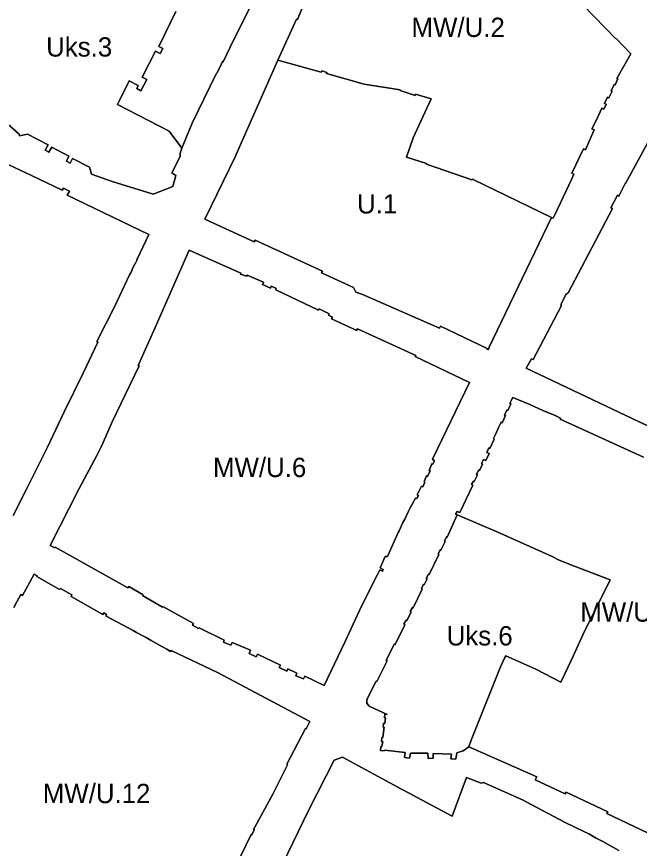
# Model space of a CAD drawing. Extents: x 7423367 to 7424726, y 5546744 to 5548391.
# Drawn here: x 7423927 to 7424088.2, y 5547952.8 to 5548168.2 of the extents above; entities that cross this region are included whole.
import ezdxf

# ---------------------------------------------------------------- set-up
doc = ezdxf.new("R2010")
doc.units = 0
doc.layers.add('linie_rozgraniczajace', color=7, linetype='Continuous')
doc.layers.add('oznaczenia_przeznaczen', color=7, linetype='Continuous')

msp = doc.modelspace()

# ---------------------------------------------------------------- linework, layer by layer
at = {"layer": 'linie_rozgraniczajace'}
for points in [[(7424003.19, 5548176.02), (7423999.73, 5548167.51), (7423999.51, 5548167.58), (7423994.64, 5548156.97), (7423983.83, 5548132.55), (7423983.76, 5548132.31), (7423975.74, 5548115.8), (7423988.5, 5548109.91), (7423988.77, 5548110.31), (7424006.16, 5548102.33), (7424005.96, 5548101.91), (7424014.24, 5548098.09), (7424014.8, 5548096.87), (7424016.34, 5548096.32), (7424036.46, 5548087.52), (7424036.71, 5548088.08), (7424048.82, 5548082.3), (7424048.77, 5548082.15), (7424049.19, 5548082), (7424049.38, 5548082.39), (7424049.28, 5548082.44), (7424065.51, 5548116.2), (7424065.9, 5548116.05), (7424066.35, 5548116.88), (7424070.65, 5548126.07), (7424071.24, 5548127.45), (7424070.72, 5548127.67), (7424073.78, 5548133.99), (7424074.27, 5548133.75), (7424076.5, 5548138.89), (7424075.92, 5548139.15), (7424077.25, 5548141.67), (7424078.55, 5548144.53), (7424079, 5548144.31), (7424079.63, 5548145.59), (7424079.24, 5548145.78), (7424079.99, 5548147.37), (7424080.34, 5548147.2), (7424081.19, 5548148.92), (7424080.9, 5548149.06), (7424081.71, 5548150.66), (7424081.98, 5548150.55), (7424082.62, 5548152.12), (7424082.42, 5548152.2), (7424086.01, 5548158.62), (7424082.2, 5548162.54), (7424082.1, 5548162.45), (7424073.67, 5548171.21)], [(7424073.67, 5548171.21), (7424082.1, 5548162.45), (7424082.2, 5548162.54), (7424086.01, 5548158.62), (7424082.42, 5548152.2), (7424082.62, 5548152.12), (7424081.98, 5548150.55), (7424081.71, 5548150.66), (7424080.9, 5548149.06), (7424081.19, 5548148.92), (7424080.34, 5548147.2), (7424079.99, 5548147.37), (7424079.24, 5548145.78), (7424079.63, 5548145.59), (7424079, 5548144.31), (7424078.55, 5548144.53), (7424077.25, 5548141.67), (7424075.92, 5548139.15), (7424076.5, 5548138.89), (7424074.27, 5548133.75), (7424073.78, 5548133.99), (7424070.72, 5548127.67), (7424071.24, 5548127.45), (7424070.65, 5548126.07), (7424066.35, 5548116.88), (7424065.9, 5548116.05), (7424065.51, 5548116.2), (7424045.18, 5548126.03), (7424044.95, 5548126.11), (7424044.88, 5548125.95), (7424033.08, 5548130.03), (7424033.14, 5548130.2), (7424027.94, 5548131.81), (7424029.66, 5548136.83), (7424032.73, 5548143.39), (7424034.34, 5548146.95), (7424030.28, 5548148.18), (7424030.19, 5548147.85), (7424026.28, 5548149.12), (7424026.31, 5548149.25), (7424016.95, 5548150.75), (7424007.21, 5548153.49), (7424007.34, 5548153.8), (7424006.03, 5548154.22), (7424005.87, 5548153.89), (7423994.64, 5548156.97), (7423999.51, 5548167.58), (7423999.73, 5548167.51), (7424003.19, 5548176.02)], [(7423918.17, 5548146.1), (7423927.64, 5548137.8), (7423927.77, 5548137.36), (7423929.82, 5548137.78), (7423935.15, 5548135.03), (7423934.4, 5548133.64), (7423935.37, 5548133.12), (7423936.1, 5548134.43), (7423940.56, 5548132.06), (7423939.91, 5548130.76), (7423940.91, 5548130.26), (7423941.51, 5548131.46), (7423945.92, 5548129.26), (7423946.39, 5548127.41), (7423951.76, 5548125.57), (7423962.14, 5548122.36), (7423962.41, 5548122.28), (7423967.48, 5548124.28), (7423968.22, 5548127.09), (7423967.24, 5548127.78), (7423969.33, 5548131.97), (7423969.39, 5548132.86), (7423969.78, 5548134.19), (7423972.47, 5548140.65), (7423978.69, 5548153.44), (7423978.76, 5548153.53), (7423978.82, 5548153.61), (7423979.76, 5548155.37), (7423980.33, 5548156.58), (7423980.53, 5548156.49), (7423983.16, 5548162.13), (7423989.62, 5548175.07)], [(7423989.62, 5548175.07), (7423983.16, 5548162.13), (7423980.53, 5548156.49), (7423980.33, 5548156.58), (7423979.76, 5548155.37), (7423978.82, 5548153.61), (7423978.76, 5548153.53), (7423978.69, 5548153.44), (7423972.47, 5548140.65), (7423969.78, 5548134.19), (7423966.54, 5548138.57), (7423953.16, 5548145.44), (7423953.66, 5548146.48), (7423956.13, 5548151.59), (7423958.5, 5548150.36), (7423958.11, 5548149.63), (7423959.2, 5548149.06), (7423960.72, 5548151.95), (7423959.54, 5548152.58), (7423962.98, 5548159.27), (7423964.18, 5548158.65), (7423964.86, 5548159.95), (7423963.82, 5548160.49), (7423968.21, 5548169.56)], [(7423968.21, 5548169.56), (7423963.82, 5548160.49), (7423964.86, 5548159.95), (7423964.18, 5548158.65), (7423962.98, 5548159.27), (7423959.54, 5548152.58), (7423960.72, 5548151.95), (7423959.2, 5548149.06), (7423958.11, 5548149.63), (7423958.5, 5548150.36), (7423956.13, 5548151.59), (7423953.66, 5548146.48), (7423953.16, 5548145.44), (7423966.54, 5548138.57), (7423969.78, 5548134.19), (7423969.39, 5548132.86), (7423969.33, 5548131.97), (7423967.24, 5548127.78), (7423968.22, 5548127.09), (7423967.48, 5548124.28), (7423962.41, 5548122.28), (7423962.14, 5548122.36), (7423951.76, 5548125.57), (7423946.39, 5548127.41), (7423945.92, 5548129.26), (7423941.51, 5548131.46), (7423940.91, 5548130.26), (7423939.91, 5548130.76), (7423940.56, 5548132.06), (7423936.1, 5548134.43), (7423935.37, 5548133.12), (7423934.4, 5548133.64), (7423935.15, 5548135.03), (7423929.82, 5548137.78), (7423927.77, 5548137.36), (7423927.64, 5548137.8), (7423918.17, 5548146.1)], [(7424090.24, 5548062.32), (7424088.17, 5548063.25), (7424058.95, 5548077.17), (7424060.29, 5548079.6), (7424060.73, 5548079.4), (7424067.99, 5548093.25), (7424067.99, 5548093.87), (7424069.27, 5548096.37), (7424069.8, 5548096.72), (7424073.3, 5548103.4), (7424081.29, 5548118.54), (7424080.88, 5548118.7), (7424082.56, 5548121.98), (7424082.95, 5548121.78), (7424084.54, 5548125.06), (7424084.67, 5548124.99), (7424090.84, 5548136.42)], [(7424090.84, 5548136.42), (7424084.67, 5548124.99), (7424084.54, 5548125.06), (7424082.95, 5548121.78), (7424082.56, 5548121.98), (7424080.88, 5548118.7), (7424081.29, 5548118.54), (7424073.3, 5548103.4), (7424069.8, 5548096.72), (7424069.27, 5548096.37), (7424067.99, 5548093.87), (7424067.99, 5548093.25), (7424060.73, 5548079.4), (7424060.29, 5548079.6), (7424058.95, 5548077.17), (7424088.17, 5548063.25), (7424090.24, 5548062.32)], [(7423922.01, 5548131.22), (7423930.85, 5548127.09), (7423938.84, 5548123.29), (7423939.13, 5548123.84), (7423940.68, 5548123.04), (7423940.15, 5548122.03), (7423961.23, 5548111.84), (7423958.12, 5548105.29), (7423958.19, 5548105.25), (7423957.68, 5548104.22), (7423957.63, 5548104.24), (7423956.93, 5548102.78), (7423957, 5548102.74), (7423956.54, 5548101.77), (7423956.47, 5548101.8), (7423956.27, 5548101.4), (7423952.32, 5548093.08), (7423947.8, 5548084.06), (7423948.08, 5548083.92), (7423944.27, 5548075.86), (7423939.3, 5548065.9), (7423934.99, 5548056.7), (7423931.08, 5548048.8), (7423929.48, 5548045.71), (7423926.14, 5548039.05)], [(7423926.14, 5548039.05), (7423929.48, 5548045.71), (7423931.08, 5548048.8), (7423934.99, 5548056.7), (7423939.3, 5548065.9), (7423944.27, 5548075.86), (7423948.08, 5548083.92), (7423947.8, 5548084.06), (7423952.32, 5548093.08), (7423956.27, 5548101.4), (7423956.47, 5548101.8), (7423956.54, 5548101.77), (7423957, 5548102.74), (7423956.93, 5548102.78), (7423957.63, 5548104.24), (7423957.68, 5548104.22), (7423958.19, 5548105.25), (7423958.12, 5548105.29), (7423961.23, 5548111.84), (7423940.15, 5548122.03), (7423940.68, 5548123.04), (7423939.13, 5548123.84), (7423938.84, 5548123.29), (7423930.85, 5548127.09), (7423922.01, 5548131.22)], [(7424089.25, 5548054.14), (7424067.71, 5548063.98), (7424067.84, 5548064.27), (7424066.42, 5548064.89), (7424063.24, 5548066.21), (7424059.91, 5548067.76), (7424055.5, 5548069.62), (7424054.73, 5548068.11), (7424054.98, 5548067.99), (7424054.17, 5548066.18), (7424053.9, 5548066.31), (7424053.3, 5548065.02), (7424053.53, 5548064.91), (7424052.68, 5548063.07), (7424052.44, 5548063.18), (7424051.87, 5548061.97), (7424050.97, 5548060.03), (7424050.43, 5548058.94), (7424050.66, 5548058.82), (7424049.54, 5548056.39), (7424049.27, 5548056.52), (7424048.73, 5548055.37), (7424049.33, 5548055.09), (7424048.49, 5548053.23), (7424047.89, 5548053.53), (7424047.37, 5548052.46), (7424047.61, 5548052.34), (7424046.82, 5548050.67), (7424046.59, 5548050.78), (7424046.05, 5548049.67), (7424046.31, 5548049.54), (7424045.48, 5548047.81), (7424045.25, 5548047.92), (7424044.8, 5548047.03), (7424045.14, 5548046.88), (7424041.78, 5548039.84), (7424041.04, 5548040.08), (7424040.67, 5548039.4), (7424041.08, 5548039.21), (7424038.48, 5548033.42), (7424038.31, 5548033.5), (7424037.76, 5548032.37), (7424037.94, 5548032.29), (7424036.87, 5548030.07), (7424036.68, 5548030.16), (7424036.15, 5548029), (7424036.33, 5548028.96), (7424033.82, 5548023.76), (7424033.63, 5548023.85), (7424033.06, 5548022.68), (7424033.26, 5548022.59), (7424032.55, 5548021.1), (7424032.34, 5548021.2), (7424031.79, 5548020.03), (7424031.99, 5548019.93), (7424029.68, 5548015.1), (7424029.46, 5548015.2), (7424028.93, 5548014.13), (7424029.16, 5548014.02), (7424028.05, 5548011.81), (7424027.83, 5548011.93), (7424027.29, 5548010.86), (7424027.51, 5548010.74), (7424025, 5548005.64), (7424024.79, 5548005.74), (7424022.69, 5548001.51), (7424022.91, 5548001.4), (7424020.27, 5547996.03), (7424020.05, 5547996.13), (7424017.69, 5547991.38), (7424017.71, 5547990.4), (7424018.28, 5547989.68), (7424022.95, 5547987.45), (7424022.36, 5547987.53), (7424022.24, 5547986.61), (7424022.52, 5547986.58), (7424022.33, 5547985.19), (7424022.03, 5547985.23), (7424021.92, 5547984.22), (7424022.2, 5547984.2), (7424021.86, 5547981.52), (7424021.57, 5547981.52), (7424021.49, 5547980.47), (7424021.79, 5547980.45), (7424021.58, 5547979.16), (7424021.31, 5547979.18), (7424021.23, 5547978.17), (7424022.21, 5547978.06), (7424022.28, 5547978.28), (7424027.59, 5547977.64), (7424027.42, 5547976.32), (7424028.75, 5547976.14), (7424028.94, 5547977.45), (7424033.51, 5547977.46), (7424033.57, 5547976.12), (7424034.87, 5547976.18), (7424034.89, 5547977.4), (7424039.56, 5547977.23), (7424039.4, 5547975.96), (7424040.71, 5547975.88), (7424040.98, 5547977.54), (7424042.64, 5547978.08), (7424044.04, 5547979.13), (7424061.65, 5547971.38), (7424061.27, 5547970.58), (7424069.01, 5547966.94), (7424069.24, 5547967.38), (7424080.03, 5547962.26), (7424079.83, 5547961.85), (7424092.32, 5547955.87)], [(7424092.32, 5547955.87), (7424079.83, 5547961.85), (7424080.03, 5547962.26), (7424069.24, 5547967.38), (7424069.01, 5547966.94), (7424061.27, 5547970.58), (7424061.65, 5547971.38), (7424044.04, 5547979.13), (7424044.69, 5547980.82), (7424052.24, 5547999.79), (7424053.43, 5548002.26), (7424053.65, 5548002.71), (7424061.43, 5547999.21), (7424067.9, 5547995.9), (7424068.99, 5547998.17), (7424071.1, 5548002.6), (7424073.69, 5548008.28), (7424075.44, 5548011.81), (7424079.87, 5548020.74), (7424080.69, 5548022.4), (7424070.04, 5548026.38), (7424067.33, 5548027.53), (7424065.69, 5548028.41), (7424051.6, 5548034.75), (7424041.08, 5548039.21), (7424040.67, 5548039.4), (7424041.04, 5548040.08), (7424041.78, 5548039.84), (7424045.14, 5548046.88), (7424044.8, 5548047.03), (7424045.25, 5548047.92), (7424045.48, 5548047.81), (7424046.31, 5548049.54), (7424046.05, 5548049.67), (7424046.59, 5548050.78), (7424046.82, 5548050.67), (7424047.61, 5548052.34), (7424047.37, 5548052.46), (7424047.89, 5548053.53), (7424048.49, 5548053.23), (7424049.33, 5548055.09), (7424048.73, 5548055.37), (7424049.27, 5548056.52), (7424049.54, 5548056.39), (7424050.66, 5548058.82), (7424050.43, 5548058.94), (7424050.97, 5548060.03), (7424051.87, 5548061.97), (7424052.44, 5548063.18), (7424052.68, 5548063.07), (7424053.53, 5548064.91), (7424053.3, 5548065.02), (7424053.9, 5548066.31), (7424054.17, 5548066.18), (7424054.98, 5548067.99), (7424054.73, 5548068.11), (7424055.5, 5548069.62), (7424059.91, 5548067.76), (7424063.24, 5548066.21), (7424066.42, 5548064.89), (7424067.84, 5548064.27), (7424067.71, 5548063.98), (7424089.25, 5548054.14)], [(7423926.3, 5548015.23), (7423927.11, 5548016.65), (7423928.13, 5548018.54), (7423928.52, 5548018.33), (7423931.54, 5548023.87), (7423932.37, 5548023.44), (7423932.28, 5548023.27), (7423938.14, 5548019.84), (7423938.34, 5548020.12), (7423941.33, 5548018.46), (7423941.17, 5548018.08), (7423949.35, 5548013.42), (7423949.57, 5548013.81), (7423950.3, 5548013.4), (7423950.16, 5548012.99), (7423957.15, 5548009.26), (7423958.03, 5548008.76), (7423959.53, 5548007.94), (7423960.52, 5548007.41), (7423961.86, 5548006.68), (7423964.62, 5548005.12), (7423965.91, 5548004.37), (7423966.88, 5548003.76), (7423967.04, 5548004.07), (7423979.03, 5547998.32), (7423981.96, 5547996.81), (7424002.91, 5547985.65), (7424002, 5547983.75), (7424001.78, 5547983.86), (7423996.93, 5547974.64), (7423997.15, 5547974.46), (7423993.33, 5547966.87), (7423988.69, 5547958.27), (7423988.35, 5547957.68), (7423988.54, 5547957.58), (7423987.92, 5547956.3), (7423987.74, 5547956.39), (7423983.64, 5547948.01)], [(7423983.64, 5547948.01), (7423987.74, 5547956.39), (7423987.92, 5547956.3), (7423988.54, 5547957.58), (7423988.35, 5547957.68), (7423988.69, 5547958.27), (7423993.33, 5547966.87), (7423997.15, 5547974.46), (7423996.93, 5547974.64), (7424001.78, 5547983.86), (7424002, 5547983.75), (7424002.91, 5547985.65), (7423981.96, 5547996.81), (7423979.03, 5547998.32), (7423967.04, 5548004.07), (7423966.88, 5548003.76), (7423965.91, 5548004.37), (7423964.62, 5548005.12), (7423961.86, 5548006.68), (7423960.52, 5548007.41), (7423959.53, 5548007.94), (7423958.03, 5548008.76), (7423957.15, 5548009.26), (7423950.16, 5548012.99), (7423950.3, 5548013.4), (7423949.57, 5548013.81), (7423949.35, 5548013.42), (7423941.17, 5548018.08), (7423941.33, 5548018.46), (7423938.34, 5548020.12), (7423938.14, 5548019.84), (7423932.28, 5548023.27), (7423932.37, 5548023.44), (7423931.54, 5548023.87), (7423928.52, 5548018.33), (7423928.13, 5548018.54), (7423927.11, 5548016.65), (7423926.3, 5548015.23)], [(7423993.29, 5547943.33), (7424002.7, 5547962.78), (7424009.23, 5547975.62), (7424011.37, 5547976.47), (7424026.69, 5547968.15), (7424028.77, 5547967.02), (7424030.56, 5547966.05), (7424039.78, 5547961.19), (7424043.49, 5547971.15), (7424047.26, 5547969.66), (7424047.89, 5547969.87), (7424058.14, 5547965.31), (7424060.22, 5547964.16), (7424069.04, 5547959.48), (7424073.85, 5547957.18), (7424075.33, 5547956.45), (7424076.9, 5547955.58), (7424078.23, 5547954.89), (7424078.76, 5547954.61), (7424082.89, 5547952.26)], [(7424082.89, 5547952.26), (7424078.76, 5547954.61), (7424078.23, 5547954.89), (7424076.9, 5547955.58), (7424075.33, 5547956.45), (7424073.85, 5547957.18), (7424069.04, 5547959.48), (7424060.22, 5547964.16), (7424058.14, 5547965.31), (7424047.89, 5547969.87), (7424047.26, 5547969.66), (7424043.49, 5547971.15), (7424039.78, 5547961.19), (7424030.56, 5547966.05), (7424028.77, 5547967.02), (7424026.69, 5547968.15), (7424011.37, 5547976.47), (7424009.23, 5547975.62), (7424002.7, 5547962.78), (7423993.29, 5547943.33)]]:
    msp.add_lwpolyline(points, dxfattribs=at)
for points in [[(7423975.74, 5548115.8), (7423983.76, 5548132.31), (7423983.83, 5548132.55), (7423994.64, 5548156.97), (7424005.87, 5548153.89), (7424006.03, 5548154.22), (7424007.34, 5548153.8), (7424007.21, 5548153.49), (7424016.95, 5548150.75), (7424026.31, 5548149.25), (7424026.28, 5548149.12), (7424030.19, 5548147.85), (7424030.28, 5548148.18), (7424034.34, 5548146.95), (7424032.73, 5548143.39), (7424029.66, 5548136.83), (7424027.94, 5548131.81), (7424033.14, 5548130.2), (7424033.08, 5548130.03), (7424044.88, 5548125.95), (7424044.95, 5548126.11), (7424045.18, 5548126.03), (7424065.51, 5548116.2), (7424049.28, 5548082.44), (7424049.38, 5548082.39), (7424049.19, 5548082), (7424048.77, 5548082.15), (7424048.82, 5548082.3), (7424036.71, 5548088.08), (7424036.46, 5548087.52), (7424016.34, 5548096.32), (7424014.8, 5548096.87), (7424014.24, 5548098.09), (7424005.96, 5548101.91), (7424006.16, 5548102.33), (7423988.77, 5548110.31), (7423988.5, 5548109.91)], [(7423935.7, 5548031.28), (7423943.15, 5548045.84), (7423947.87, 5548054.71), (7423948.87, 5548056.79), (7423950.1, 5548059.46), (7423950.29, 5548059.9), (7423951.49, 5548062.65), (7423951.79, 5548063.33), (7423958.76, 5548077.75), (7423958.5, 5548077.86), (7423962.87, 5548087.75), (7423971.69, 5548107.76), (7423985.09, 5548101.79), (7423984.98, 5548101.51), (7423986.5, 5548101), (7423986.68, 5548101.3), (7423990.93, 5548099.45), (7423990.7, 5548098.84), (7423992.73, 5548097.95), (7423992.95, 5548098.44), (7423994.16, 5548097.9), (7423994.14, 5548097.45), (7424005.13, 5548092.17), (7424005.3, 5548092.53), (7424007.96, 5548091.26), (7424007.79, 5548090.9), (7424008.76, 5548090.43), (7424008.55, 5548089.98), (7424014.12, 5548087.4), (7424015.04, 5548086.95), (7424015.25, 5548087.4), (7424030.32, 5548080.47), (7424030.22, 5548080.25), (7424044.27, 5548073.5), (7424034.67, 5548053.63), (7424035.15, 5548053.2), (7424034.76, 5548052.31), (7424034.53, 5548052.41), (7424033.81, 5548050.72), (7424034.07, 5548050.59), (7424033.35, 5548049.16), (7424033.08, 5548049.29), (7424032.48, 5548047.81), (7424032.73, 5548047.7), (7424032.2, 5548046.46), (7424031.83, 5548046.62), (7424030.74, 5548044.4), (7424031.09, 5548044.18), (7424030.62, 5548043.45), (7424030.28, 5548043.55), (7424028.92, 5548041), (7424028.45, 5548040.12), (7424027.53, 5548038.08), (7424027, 5548037.18), (7424026.02, 5548035.09), (7424025.78, 5548034.63), (7424023.01, 5548028.39), (7424022.45, 5548028.37), (7424021.17, 5548025.47), (7424021.93, 5548025.05), (7424021.69, 5548024.63), (7424021.04, 5548024.99), (7424020.34, 5548023.59), (7424016.28, 5548015.51), (7424011.95, 5548006.2), (7424006.63, 5547995.03), (7424001.64, 5547997.4), (7424001.28, 5547996.68), (7423999.29, 5547997.53), (7423999.57, 5547998.18), (7423997.26, 5547999.3), (7423996.96, 5547998.73), (7423995.02, 5547999.67), (7423995.32, 5548000.3), (7423989.38, 5548003.07), (7423989.06, 5548002.45), (7423987.2, 5548003.32), (7423987.58, 5548004.14), (7423982.81, 5548006.14), (7423982.51, 5548005.45), (7423980.61, 5548006.24), (7423980.77, 5548006.71), (7423974.26, 5548009.9), (7423974.09, 5548009.72), (7423972.53, 5548010.63), (7423972.78, 5548011.06), (7423964.83, 5548015.45), (7423964.76, 5548015.32), (7423959.62, 5548018.29), (7423959.75, 5548018.5), (7423956.03, 5548020.6), (7423955.78, 5548020.26), (7423936.99, 5548030.79), (7423936.92, 5548030.66)], [(7423935.7, 5548031.28), (7423936.92, 5548030.66), (7423936.99, 5548030.79), (7423955.78, 5548020.26), (7423956.03, 5548020.6), (7423959.75, 5548018.5), (7423959.62, 5548018.29), (7423964.76, 5548015.32), (7423964.83, 5548015.45), (7423972.78, 5548011.06), (7423972.53, 5548010.63), (7423974.09, 5548009.72), (7423974.26, 5548009.9), (7423980.77, 5548006.71), (7423980.61, 5548006.24), (7423982.51, 5548005.45), (7423982.81, 5548006.14), (7423987.58, 5548004.14), (7423987.2, 5548003.32), (7423989.06, 5548002.45), (7423989.38, 5548003.07), (7423995.32, 5548000.3), (7423995.02, 5547999.67), (7423996.96, 5547998.73), (7423997.26, 5547999.3), (7423999.57, 5547998.18), (7423999.29, 5547997.53), (7424001.28, 5547996.68), (7424001.64, 5547997.4), (7424006.63, 5547995.03), (7424011.95, 5548006.2), (7424016.28, 5548015.51), (7424020.34, 5548023.59), (7424021.04, 5548024.99), (7424021.69, 5548024.63), (7424021.93, 5548025.05), (7424021.17, 5548025.47), (7424022.45, 5548028.37), (7424023.01, 5548028.39), (7424025.78, 5548034.63), (7424026.02, 5548035.09), (7424027, 5548037.18), (7424027.53, 5548038.08), (7424028.45, 5548040.12), (7424028.92, 5548041), (7424030.28, 5548043.55), (7424030.62, 5548043.45), (7424031.09, 5548044.18), (7424030.74, 5548044.4), (7424031.83, 5548046.62), (7424032.2, 5548046.46), (7424032.73, 5548047.7), (7424032.48, 5548047.81), (7424033.08, 5548049.29), (7424033.35, 5548049.16), (7424034.07, 5548050.59), (7424033.81, 5548050.72), (7424034.53, 5548052.41), (7424034.76, 5548052.31), (7424035.15, 5548053.2), (7424034.67, 5548053.63), (7424044.27, 5548073.5), (7424030.22, 5548080.25), (7424030.32, 5548080.47), (7424015.25, 5548087.4), (7424015.04, 5548086.95), (7424014.12, 5548087.4), (7424008.55, 5548089.98), (7424008.76, 5548090.43), (7424007.79, 5548090.9), (7424007.96, 5548091.26), (7424005.3, 5548092.53), (7424005.13, 5548092.17), (7423994.14, 5548097.45), (7423994.16, 5548097.9), (7423992.95, 5548098.44), (7423992.73, 5548097.95), (7423990.7, 5548098.84), (7423990.93, 5548099.45), (7423986.68, 5548101.3), (7423986.5, 5548101), (7423984.98, 5548101.51), (7423985.09, 5548101.79), (7423971.69, 5548107.76), (7423962.87, 5548087.75), (7423958.5, 5548077.86), (7423958.76, 5548077.75), (7423951.79, 5548063.33), (7423951.49, 5548062.65), (7423950.29, 5548059.9), (7423950.1, 5548059.46), (7423948.87, 5548056.79), (7423947.87, 5548054.71), (7423943.15, 5548045.84)], [(7424017.71, 5547990.4), (7424017.69, 5547991.38), (7424020.05, 5547996.13), (7424020.27, 5547996.03), (7424022.91, 5548001.4), (7424022.69, 5548001.51), (7424024.79, 5548005.74), (7424025, 5548005.64), (7424027.51, 5548010.74), (7424027.29, 5548010.86), (7424027.83, 5548011.93), (7424028.05, 5548011.81), (7424029.16, 5548014.02), (7424028.93, 5548014.13), (7424029.46, 5548015.2), (7424029.68, 5548015.1), (7424031.99, 5548019.93), (7424031.79, 5548020.03), (7424032.34, 5548021.2), (7424032.55, 5548021.1), (7424033.26, 5548022.59), (7424033.06, 5548022.68), (7424033.63, 5548023.85), (7424033.82, 5548023.76), (7424036.33, 5548028.96), (7424036.15, 5548029), (7424036.68, 5548030.16), (7424036.87, 5548030.07), (7424037.94, 5548032.29), (7424037.76, 5548032.37), (7424038.31, 5548033.5), (7424038.48, 5548033.42), (7424041.08, 5548039.21), (7424051.6, 5548034.75), (7424065.69, 5548028.41), (7424067.33, 5548027.53), (7424070.04, 5548026.38), (7424080.69, 5548022.4), (7424079.87, 5548020.74), (7424075.44, 5548011.81), (7424073.69, 5548008.28), (7424071.1, 5548002.6), (7424068.99, 5547998.17), (7424067.9, 5547995.9), (7424061.43, 5547999.21), (7424053.65, 5548002.71), (7424053.43, 5548002.26), (7424052.24, 5547999.79), (7424044.69, 5547980.82), (7424044.04, 5547979.13), (7424042.64, 5547978.08), (7424040.98, 5547977.54), (7424040.71, 5547975.88), (7424039.4, 5547975.96), (7424039.56, 5547977.23), (7424034.89, 5547977.4), (7424034.87, 5547976.18), (7424033.57, 5547976.12), (7424033.51, 5547977.46), (7424028.94, 5547977.45), (7424028.75, 5547976.14), (7424027.42, 5547976.32), (7424027.59, 5547977.64), (7424022.28, 5547978.28), (7424022.21, 5547978.06), (7424021.23, 5547978.17), (7424021.31, 5547979.18), (7424021.58, 5547979.16), (7424021.79, 5547980.45), (7424021.49, 5547980.47), (7424021.57, 5547981.52), (7424021.86, 5547981.52), (7424022.2, 5547984.2), (7424021.92, 5547984.22), (7424022.03, 5547985.23), (7424022.33, 5547985.19), (7424022.52, 5547986.58), (7424022.24, 5547986.61), (7424022.36, 5547987.53), (7424022.95, 5547987.45), (7424018.28, 5547989.68)]]:
    msp.add_lwpolyline(points, close=True, dxfattribs=at)

# ---------------------------------------------------------------- texts
at = {"layer": 'oznaczenia_przeznaczen'}
for s, p in [('MW/U.2', (7424029.25, 5548162.97)), ('Uks.3', (7423934.67, 5548157.89)), ('U.1', (7424015.15, 5548117.25)), ('MW/U.6', (7423977.86, 5548048.98)), ('MW/U.7', (7424072.93, 5548011.53)), ('Uks.6', (7424038.34, 5548005.37)), ('MW/U.12', (7423933.8, 5547964.53))]:
    msp.add_text(s, height=5, dxfattribs=at).set_placement(p)

doc.saveas('drawing.dxf')
